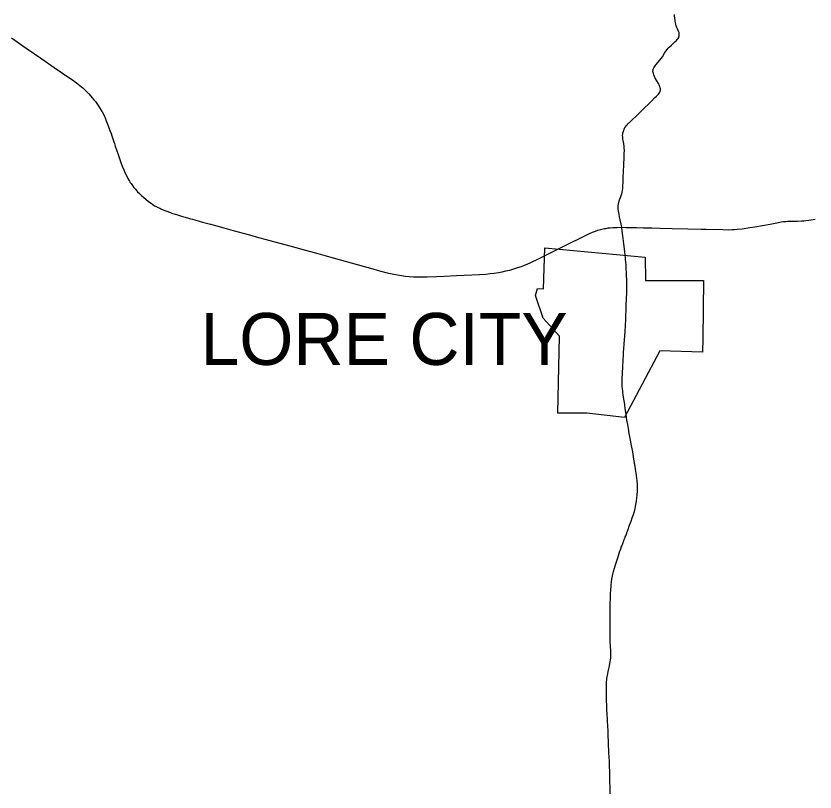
# Model space of a CAD drawing. Extents: x 2125567 to 2397567, y 653347 to 829347.
# Drawn here: x 2246984 to 2264193, y 713813 to 730535 of the extents above; entities that cross this region are included whole.
import ezdxf

# ---------------------------------------------------------------- set-up
doc = ezdxf.new("R2010")
doc.units = 0
for name, color, linetype in [('GM_X_Corporation', 7, 'Continuous'), ('GM_X_Corporation_Text', 7, 'Continuous'), ('GM_X_State_Route', 7, 'Continuous')]:
    doc.layers.add(name, color=color, linetype=linetype)

msp = doc.modelspace()

# ---------------------------------------------------------------- linework, layer by layer
at = {"layer": 'GM_X_Corporation'}
msp.add_lwpolyline([(2260537, 725336), (2260545, 724835), (2261789, 724838), (2261774, 723584), (2261769, 723290), (2260852, 723323), (2260092, 721883), (2259280, 721978), (2258655, 721979), (2258686, 723634), (2258337, 724024), (2258169, 724513), (2258219, 724659), (2258345, 724656), (2258373, 725538)], close=True, dxfattribs=at)
at = {"layer": 'GM_X_State_Route'}
msp.add_line((2260029, 725981), (2260128, 725980), dxfattribs=at)
for points in [[(2260154, 728201), (2260169, 728216), (2260182, 728230), (2260196, 728243), (2260232, 728277), (2260251, 728295), (2260271, 728312), (2260330, 728368), (2260356, 728393), (2260384, 728421), (2260409, 728447), (2260432, 728470), (2260492, 728530), (2260530, 728566), (2260604, 728636), (2260677, 728709), (2260737, 728769), (2260777, 728807), (2260806, 728834), (2260822, 728851), (2260838, 728872), (2260848, 728890), (2260855, 728906), (2260860, 728925), (2260862, 728939), (2260863, 728962), (2260859, 728989), (2260853, 729012), (2260846, 729031), (2260838, 729049), (2260821, 729081), (2260786, 729140), (2260753, 729197), (2260735, 729233), (2260722, 729264), (2260712, 729292), (2260706, 729316), (2260702, 729340), (2260705, 729374), (2260709, 729388), (2260722, 729417), (2260733, 729436), (2260751, 729464), (2260773, 729492), (2260850, 729580), (2260881, 729619), (2260907, 729657), (2260951, 729730), (2260980, 729777), (2261009, 729816), (2261033, 729842), (2261053, 729862), (2261103, 729909), (2261176, 729975), (2261212, 730009), (2261227, 730027), (2261243, 730048), (2261256, 730072), (2261261, 730084), (2261267, 730107), (2261268, 730117), (2261269, 730148), (2261264, 730177), (2261261, 730187), (2261245, 730224), (2261228, 730256), (2261213, 730288), (2261201, 730325), (2261193, 730357), (2261187, 730388), (2261178, 730440), (2261172, 730492), (2261168, 730528), (2261164, 730566)], [(2246887, 730063), (2247206, 729843), (2247537, 729613), (2247807, 729427), (2247965, 729318), (2248034, 729270), (2248055, 729255), (2248113, 729215), (2248143, 729195), (2248221, 729141), (2248237, 729129), (2248288, 729093), (2248322, 729067), (2248358, 729039), (2248396, 729007), (2248420, 728985), (2248450, 728959), (2248499, 728911), (2248516, 728894), (2248550, 728859), (2248599, 728806), (2248627, 728773), (2248662, 728730), (2248695, 728689), (2248737, 728630), (2248767, 728587), (2248790, 728551), (2248811, 728514), (2248838, 728468), (2248865, 728416), (2248887, 728372), (2248901, 728342), (2248928, 728278), (2248948, 728226), (2248956, 728205), (2248977, 728149), (2249007, 728066), (2249030, 728001), (2249049, 727949), (2249072, 727884), (2249094, 727822), (2249106, 727785), (2249123, 727732), (2249157, 727632), (2249178, 727570), (2249199, 727504), (2249239, 727380), (2249256, 727334), (2249261, 727320), (2249270, 727297), (2249305, 727216), (2249329, 727162), (2249370, 727080), (2249396, 727031), (2249416, 726996), (2249430, 726972), (2249446, 726947), (2249462, 726924), (2249494, 726879), (2249518, 726848), (2249558, 726800), (2249604, 726749), (2249645, 726707), (2249689, 726664), (2249736, 726622), (2249781, 726585), (2249840, 726538), (2249894, 726498), (2249970, 726447)], [(2260076, 727353), (2260076, 727363), (2260081, 727454), (2260085, 727572), (2260086, 727638), (2260084, 727687), (2260080, 727736), (2260075, 727772), (2260066, 727824), (2260056, 727882), (2260051, 727920), (2260049, 727962), (2260053, 727990), (2260055, 728009), (2260059, 728028), (2260066, 728053), (2260072, 728075), (2260079, 728092), (2260083, 728101), (2260090, 728114), (2260094, 728120), (2260100, 728131), (2260108, 728145), (2260128, 728170), (2260151, 728198), (2260154, 728201)], [(2260029, 725981), (2259983, 726204), (2259972, 726262), (2259960, 726330), (2259955, 726372), (2259953, 726410), (2259955, 726446), (2259960, 726481), (2259968, 726519), (2259978, 726554), (2259984, 726572), (2260003, 726621), (2260019, 726664), (2260030, 726699), (2260038, 726731), (2260045, 726773), (2260051, 726816), (2260056, 726872), (2260059, 726944), (2260060, 726973), (2260062, 727022), (2260063, 727072), (2260066, 727167), (2260068, 727216), (2260072, 727294), (2260075, 727337), (2260075, 727343), (2260076, 727353)], [(2249970, 726447), (2250008, 726427), (2250026, 726418), (2250047, 726408), (2250079, 726393), (2250106, 726381), (2250157, 726359)], [(2250157, 726359), (2250167, 726354), (2250213, 726336), (2250310, 726298), (2250354, 726281), (2250391, 726268), (2250459, 726247), (2250502, 726234), (2250573, 726214), (2250626, 726199), (2250696, 726180), (2250743, 726167), (2250787, 726155), (2250838, 726140), (2250930, 726115), (2251002, 726095), (2251171, 726049), (2251183, 726046), (2251280, 726019), (2251462, 725969), (2251663, 725913), (2251739, 725892), (2251904, 725848), (2252063, 725804), (2252157, 725778), (2252236, 725757), (2252449, 725698), (2252635, 725647), (2252879, 725580), (2253140, 725508), (2253482, 725416), (2253635, 725373), (2253814, 725321), (2254201, 725218), (2254458, 725145), (2254616, 725101), (2254812, 725046), (2254976, 725003), (2255053, 724985), (2255119, 724971), (2255200, 724956), (2255287, 724942), (2255372, 724931), (2255453, 724922), (2255544, 724916), (2255630, 724913), (2255725, 724912), (2255839, 724915), (2256039, 724922), (2256206, 724930), (2256472, 724943), (2256967, 724966), (2257101, 724975), (2257195, 724983), (2257280, 724993), (2257374, 725007), (2257458, 725022), (2257537, 725040), (2257617, 725060), (2257705, 725085), (2257793, 725112), (2257870, 725139), (2257934, 725163), (2257995, 725188), (2258069, 725222), (2258238, 725303), (2258338, 725352), (2258364, 725365)], [(2260128, 725980), (2260134, 725980), (2260347, 725976), (2260501, 725971), (2260675, 725969), (2260859, 725964), (2261115, 725957), (2261453, 725949), (2261738, 725942), (2261840, 725940), (2262207, 725931), (2262338, 725930), (2262410, 725932), (2262461, 725934), (2262516, 725938), (2262623, 725951), (2262789, 725975), (2262899, 725992), (2263058, 726018), (2263226, 726051), (2263403, 726087), (2263465, 726097), (2263512, 726105), (2263561, 726109), (2263598, 726112), (2263731, 726113), (2263816, 726115), (2263901, 726118), (2263950, 726122), (2263996, 726127), (2264058, 726136), (2264194, 726155)], [(2258650, 725508), (2258738, 725553), (2258926, 725646), (2259119, 725743), (2259278, 725822), (2259338, 725849), (2259402, 725876), (2259464, 725899), (2259514, 725916), (2259571, 725932), (2259632, 725947), (2259661, 725953), (2259690, 725959), (2259714, 725963), (2259738, 725967), (2259784, 725972), (2259840, 725977), (2259926, 725980), (2260029, 725981)], [(2260105, 725372), (2260094, 725460), (2260073, 725622), (2260052, 725794), (2260038, 725901), (2260029, 725981)], [(2258364, 725365), (2258439, 725402), (2258625, 725495), (2258650, 725508)], [(2260137, 724778), (2260137, 724794), (2260130, 725000), (2260126, 725089), (2260122, 725171), (2260114, 725288), (2260110, 725327), (2260105, 725372)], [(2260107, 723784), (2260109, 723815), (2260113, 723890), (2260116, 723972), (2260119, 724047), (2260121, 724100), (2260123, 724175), (2260125, 724267), (2260127, 724325), (2260127, 724331), (2260130, 724414), (2260136, 724604), (2260137, 724624), (2260138, 724696), (2260138, 724717), (2260137, 724778)], [(2260039, 722734), (2260040, 722755), (2260043, 722801), (2260045, 722849), (2260048, 722887), (2260050, 722926), (2260052, 722970), (2260055, 723017), (2260058, 723074), (2260062, 723136), (2260062, 723142), (2260066, 723214), (2260070, 723289), (2260075, 723364), (2260081, 723466), (2260087, 723555), (2260090, 723586), (2260093, 723614), (2260094, 723623), (2260099, 723672), (2260103, 723708), (2260106, 723753), (2260107, 723784)], [(2260126, 721943), (2260125, 721948), (2260106, 722082), (2260097, 722143), (2260094, 722166), (2260081, 722243), (2260070, 722320), (2260063, 722370), (2260055, 722429), (2260052, 722454), (2260046, 722503), (2260042, 722542), (2260038, 722611), (2260036, 722650), (2260036, 722686), (2260037, 722713), (2260039, 722734)], [(2260192, 721540), (2260173, 721645), (2260159, 721729), (2260143, 721826), (2260134, 721887), (2260126, 721943)], [(2259783, 713775), (2259780, 713866), (2259778, 713926), (2259776, 714023), (2259773, 714133), (2259770, 714266), (2259768, 714347), (2259765, 714426), (2259763, 714475), (2259760, 714567), (2259755, 714663), (2259752, 714724), (2259748, 714818), (2259745, 714905), (2259739, 715025), (2259737, 715070), (2259734, 715134), (2259729, 715229), (2259727, 715274), (2259726, 715303), (2259724, 715345), (2259722, 715400), (2259718, 715472), (2259711, 715604), (2259707, 715659), (2259706, 715692), (2259703, 715770), (2259701, 715885), (2259701, 715954), (2259700, 716007), (2259702, 716113), (2259703, 716178), (2259704, 716194), (2259708, 716226), (2259710, 716245), (2259712, 716258), (2259718, 716296), (2259722, 716326), (2259729, 716364), (2259737, 716412), (2259744, 716441), (2259756, 716499), (2259766, 716540), (2259773, 716576), (2259782, 716628), (2259786, 716657), (2259792, 716706), (2259793, 716729), (2259794, 716755), (2259795, 716801), (2259794, 716821), (2259794, 716827), (2259794, 716837), (2259794, 716863), (2259793, 716880), (2259790, 716925), (2259783, 717086), (2259779, 717188), (2259778, 717461), (2259780, 717570), (2259780, 717630), (2259781, 717721), (2259784, 717866), (2259787, 718000), (2259790, 718095), (2259792, 718157), (2259800, 718266), (2259810, 718348), (2259817, 718400), (2259823, 718432), (2259839, 718506), (2259854, 718566), (2259876, 718638), (2259897, 718707), (2259943, 718858), (2259965, 718931), (2259981, 718978), (2259996, 719022), (2260001, 719035), (2260014, 719072), (2260020, 719087), (2260029, 719112), (2260051, 719169), (2260067, 719212), (2260073, 719226), (2260077, 719236), (2260081, 719248), (2260084, 719254), (2260089, 719269), (2260096, 719284), (2260102, 719299), (2260107, 719311), (2260115, 719332), (2260129, 719369), (2260137, 719391), (2260141, 719405), (2260153, 719435), (2260169, 719478), (2260174, 719490), (2260186, 719523), (2260200, 719560), (2260214, 719597), (2260234, 719652), (2260258, 719720), (2260271, 719757), (2260283, 719794), (2260302, 719860), (2260318, 719924), (2260326, 719962), (2260335, 720011), (2260346, 720082), (2260356, 720154), (2260362, 720209), (2260369, 720305), (2260370, 720357), (2260370, 720380), (2260368, 720455), (2260365, 720504), (2260362, 720535), (2260358, 720562), (2260346, 720647), (2260328, 720760), (2260317, 720831), (2260313, 720854), (2260311, 720870), (2260308, 720889), (2260304, 720912), (2260293, 720983), (2260274, 721096), (2260266, 721140), (2260240, 721278), (2260212, 721432), (2260205, 721471), (2260192, 721540)]]:
    msp.add_lwpolyline(points, dxfattribs=at)

# ---------------------------------------------------------------- texts
at = {"layer": 'GM_X_Corporation_Text'}
msp.add_text('LORE CITY', height=1120, rotation=0, dxfattribs=at).set_placement((2250960, 723016))

doc.saveas('drawing.dxf')
